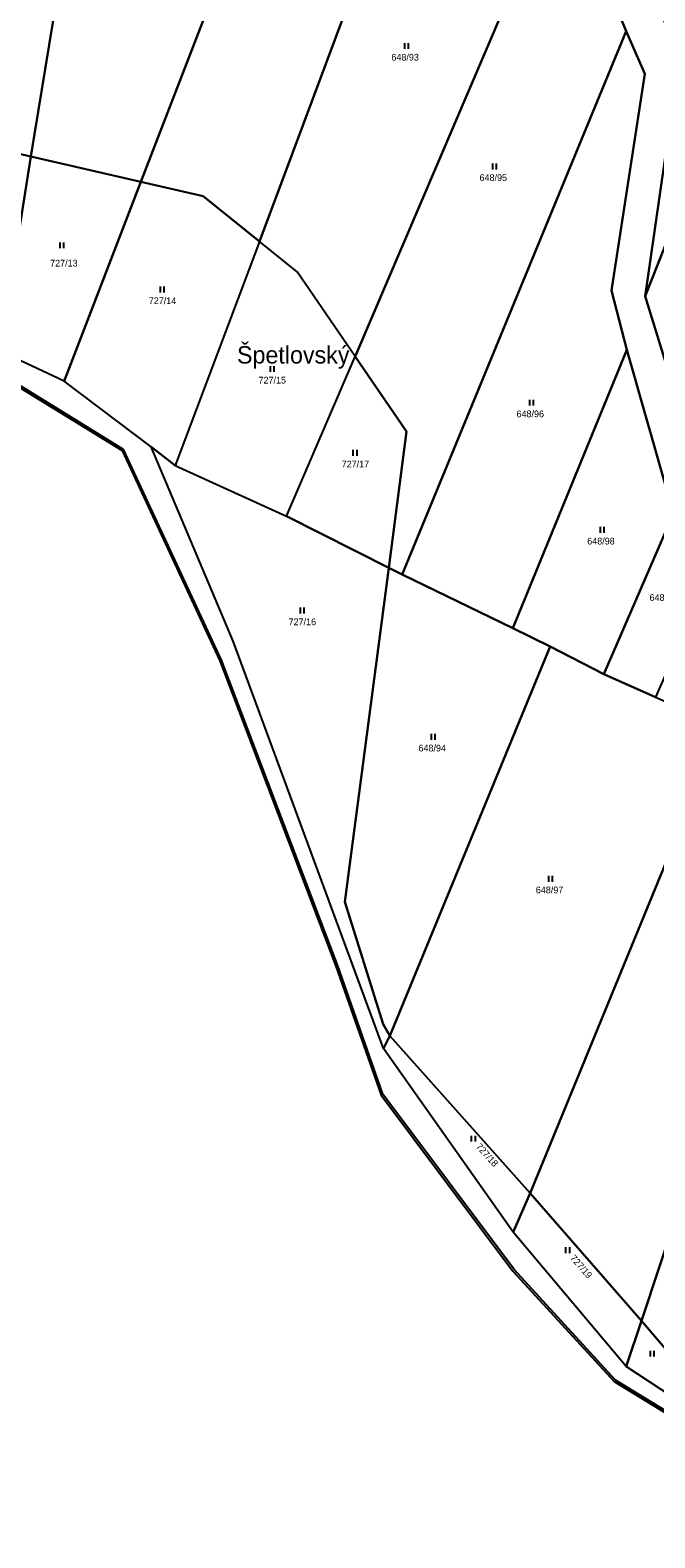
# Model space of a CAD drawing. Extents: x -654083 to -650132, y -1099819 to -1096699.
# Drawn here: x -653142.9 to -652984.9, y -1098730.3 to -1098349.3 of the extents above; entities that cross this region are included whole.
import ezdxf

# ---------------------------------------------------------------- set-up
doc = ezdxf.new("R2010")
doc.units = 0
for name, color, linetype in [('Názvy', 7, 'Continuous'), ('Obvody jako plochy', 7, 'Continuous'), ('Ostatní hranice', 7, 'Continuous'), ('Parcelní čísla', 7, 'Continuous'), ('Značky kultur', 7, 'Continuous')]:
    doc.layers.add(name, color=color, linetype=linetype)

msp = doc.modelspace()

# ---------------------------------------------------------------- linework, layer by layer
at = {"layer": 'Obvody jako plochy'}
for points in [[(-653127.95, -1098291.32), (-653142.71, -1098381.19), (-653171.11, -1098374.64), (-653176.09, -1098376.64), (-653195.41, -1098271.81), (-653177, -1098289.83), (-653131.67, -1098287.09)], [(-653091.81, -1098316.91), (-653087.77, -1098317.34), (-653114.87, -1098387.6), (-653142.71, -1098381.19), (-653127.95, -1098291.32), (-653113.07, -1098308.24)], [(-653054.32, -1098320.92), (-653084.9, -1098402.68), (-653099.09, -1098391.24), (-653114.87, -1098387.6), (-653087.77, -1098317.34)], [(-653015.1, -1098325.02), (-653060.71, -1098431.71), (-653075.36, -1098410.36), (-653084.9, -1098402.68), (-653054.32, -1098320.92)], [(-653000.43, -1098329.34), (-652992.17, -1098349.49), (-653048.81, -1098486.88), (-653052.2, -1098485.17), (-653047.69, -1098450.69), (-653060.71, -1098431.71), (-653015.1, -1098325.02)], [(-652974.53, -1098458.03), (-652973.42, -1098461.64), (-652965.91, -1098468.87), (-652965.37, -1098475.91), (-652961.88, -1098484.34), (-652968.07, -1098479.83), (-652979.25, -1098469.28), (-652981.33, -1098467.32), (-652991.98, -1098430.02), (-652995.82, -1098415.1), (-652987.44, -1098360.32), (-652992.17, -1098349.49), (-653000.43, -1098329.34), (-652998.13, -1098330.02), (-652985.77, -1098339.58), (-652978.6, -1098355.74), (-652987.34, -1098416.51)], [(-652980.88, -1098343.37), (-652970.49, -1098364.98), (-652969.4, -1098371.21), (-652987.34, -1098416.51), (-652978.6, -1098355.74), (-652985.77, -1098339.58)], [(-652992.17, -1098349.49), (-652987.44, -1098360.32), (-652995.82, -1098415.1), (-652991.98, -1098430.02), (-653020.84, -1098500.43), (-653048.81, -1098486.88)], [(-652969.4, -1098371.21), (-652966.01, -1098390.48), (-652968.37, -1098436.49), (-652967.85, -1098443.28), (-652974.53, -1098458.03), (-652987.34, -1098416.51)], [(-653142.71, -1098381.19), (-653150.53, -1098430.42), (-653165.88, -1098429.33), (-653176.09, -1098376.64), (-653171.11, -1098374.64)], [(-653114.87, -1098387.6), (-653134.3, -1098437.97), (-653150.53, -1098430.42), (-653142.71, -1098381.19)], [(-653114.87, -1098387.6), (-653099.09, -1098391.24), (-653084.9, -1098402.68), (-653106.18, -1098459.29), (-653112.26, -1098454.59), (-653134.3, -1098437.97)], [(-653106.18, -1098459.29), (-653078.02, -1098472.13), (-653060.71, -1098431.71), (-653075.36, -1098410.36), (-653084.9, -1098402.68)], [(-653060.71, -1098431.71), (-653047.69, -1098450.69), (-653052.2, -1098485.17), (-653078.02, -1098472.13)], [(-652981.33, -1098467.32), (-652979.25, -1098469.28), (-652997.77, -1098512.08), (-653011.33, -1098505.03), (-653020.84, -1098500.43), (-652991.98, -1098430.02)], [(-653053.64, -1098600.47), (-653051.91, -1098603.46), (-653053.48, -1098606.67), (-653091.55, -1098503.66), (-653112.26, -1098454.59), (-653106.18, -1098459.29), (-653078.02, -1098472.13), (-653052.2, -1098485.17), (-653063.26, -1098569.58)], [(-652979.25, -1098469.28), (-652968.07, -1098479.83), (-652984.73, -1098517.85), (-652997.77, -1098512.08)], [(-653052.2, -1098485.17), (-653048.81, -1098486.88), (-653020.84, -1098500.43), (-653011.33, -1098505.03), (-653051.91, -1098603.46), (-653053.64, -1098600.47), (-653063.26, -1098569.58)], [(-652971.47, -1098523.62), (-652968.42, -1098526.44), (-653016.39, -1098643.21), (-653051.91, -1098603.46), (-653011.33, -1098505.03), (-652997.77, -1098512.08), (-652984.73, -1098517.85)], [(-652968.42, -1098526.44), (-652942.95, -1098538.93), (-652988.24, -1098675.47), (-653016.39, -1098643.21)], [(-652936.32, -1098569.42), (-652972.96, -1098693.44), (-652988.24, -1098675.47), (-652942.95, -1098538.93), (-652913.05, -1098552.12)], [(-653051.91, -1098603.46), (-653016.39, -1098643.21), (-653020.76, -1098653.1), (-653053.48, -1098606.67)], [(-653016.39, -1098643.21), (-652988.24, -1098675.47), (-652992.14, -1098687.01), (-653020.76, -1098653.1)], [(-652988.24, -1098675.47), (-652972.96, -1098693.44), (-652974.44, -1098698.63), (-652992.14, -1098687.01)]]:
    msp.add_lwpolyline(points, close=True, dxfattribs=at)
msp.add_lwpolyline([(-653154.72, -1098433.98), (-653119.61, -1098455.53), (-653094.92, -1098508.68), (-653065.55, -1098585.87), (-653054.08, -1098618.44), (-653020.82, -1098662.91), (-652995.19, -1098690.83), (-652972.99, -1098704.39), (-652953.81, -1098730.27), (-652951.88, -1098730.34), (-652951.97, -1098722.55), (-652974.44, -1098698.63), (-652992.14, -1098687.01), (-653020.76, -1098653.1), (-653053.48, -1098606.67), (-653091.55, -1098503.66), (-653112.26, -1098454.59), (-653134.3, -1098437.97), (-653150.53, -1098430.42)], dxfattribs=at)
at = {"layer": 'Ostatní hranice'}
for p, q in [((-653119.23, -1098455.22), (-653154.51, -1098433.53)), ((-653094.45, -1098508.52), (-653119.23, -1098455.22)), ((-653065.07, -1098585.73), (-653094.45, -1098508.52)), ((-653053.67, -1098618.16), (-653065.07, -1098585.73)), ((-653020.48, -1098662.54), (-653053.67, -1098618.16)), ((-652994.81, -1098690.5), (-653020.48, -1098662.54)), ((-652972.65, -1098704.03), (-652994.81, -1098690.5))]:
    msp.add_line(p, q, dxfattribs=at)
at = {"layer": 'Značky kultur'}
for p, q in [((-653048.2, -1098352.52), (-653048.2, -1098354.02)), ((-653047.18, -1098354.02), (-653047.18, -1098352.52)), ((-653025.94, -1098382.95), (-653025.94, -1098384.45)), ((-653024.92, -1098384.45), (-653024.92, -1098382.95)), ((-653135.41, -1098402.89), (-653135.41, -1098404.39)), ((-653134.39, -1098404.39), (-653134.39, -1098402.89)), ((-653109.98, -1098414.06), (-653109.98, -1098415.56)), ((-653108.95, -1098415.56), (-653108.95, -1098414.06)), ((-653082.19, -1098434.15), (-653082.19, -1098435.65)), ((-653081.17, -1098435.65), (-653081.17, -1098434.15)), ((-653016.63, -1098442.67), (-653016.63, -1098444.17)), ((-653015.6, -1098444.17), (-653015.6, -1098442.67)), ((-653061.23, -1098455.35), (-653061.23, -1098456.85)), ((-653060.2, -1098456.85), (-653060.2, -1098455.35)), ((-652998.72, -1098474.82), (-652998.72, -1098476.32)), ((-652997.7, -1098476.32), (-652997.7, -1098474.82)), ((-653074.61, -1098495.23), (-653074.61, -1098496.73)), ((-653073.58, -1098496.73), (-653073.58, -1098495.23)), ((-653041.43, -1098527.14), (-653041.43, -1098528.64)), ((-653040.41, -1098528.64), (-653040.41, -1098527.14)), ((-653011.79, -1098563), (-653011.79, -1098564.5)), ((-653010.77, -1098564.5), (-653010.77, -1098563)), ((-653031.3, -1098628.7), (-653031.3, -1098630.2)), ((-653030.28, -1098630.2), (-653030.28, -1098628.7)), ((-653007.45, -1098656.86), (-653007.45, -1098658.36)), ((-653006.43, -1098658.36), (-653006.43, -1098656.86)), ((-652986.06, -1098683.04), (-652986.06, -1098684.54)), ((-652985.04, -1098684.54), (-652985.04, -1098683.04))]:
    msp.add_line(p, q, dxfattribs=at)

# ---------------------------------------------------------------- texts
at = {"layer": 'Názvy'}
msp.add_text('Špetlovský', height=4.4, dxfattribs=at).set_placement((-653090.57, -1098433.53))
at = {"layer": 'Parcelní čísla'}
for s, p in [('648/93', (-653051.52, -1098356.96)), ('648/95', (-653029.22, -1098387.38)), ('727/13', (-653137.84, -1098409.01)), ('727/14', (-653112.89, -1098418.5)), ('727/15', (-653085.13, -1098438.58)), ('648/96', (-653019.87, -1098447.1)), ('727/17', (-653064.1, -1098459.79)), ('648/98', (-653001.99, -1098479.26)), ('648/99', (-652986.23, -1098493.52)), ('727/16', (-653077.52, -1098499.66)), ('648/94', (-653044.67, -1098531.57)), ('648/97', (-653014.99, -1098567.43))]:
    msp.add_text(s, height=1.7, dxfattribs=at).set_placement(p)
for s, rotation, p in [('727/18', 311.985, (-653030.27, -1098631.55)), ('727/19', 311.382, (-653006.44, -1098659.72))]:
    msp.add_text(s, height=1.7, rotation=rotation, dxfattribs=at).set_placement(p)

doc.saveas('drawing.dxf')
